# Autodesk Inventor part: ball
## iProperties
Author: E. MOSS
Created: 2001-10
Part Number: ball
Document SubType Name: Modeling
Designer: E. MOSS
Control State: 0
Master: False
Checked Out: False
PropertySet Name: Design Tracking Control
Shininess: 64.0
Angle Display Precision: 2
Document Length Units: 11272
Document Angle Units: 11286
Document Time Units: 11279
Document Mass Units: 11290
Document Length Units Precision: 3
Document Angle Units Precision: 2
Compacted: False
PropertySet Name: _Private Model Information
Density: 0.0
Volumn: 0.0
Area: 0.0
PropertySet Name: Model Information
